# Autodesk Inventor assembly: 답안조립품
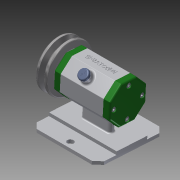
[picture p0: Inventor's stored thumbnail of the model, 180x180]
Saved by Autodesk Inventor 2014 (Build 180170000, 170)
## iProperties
Created: 2018-06
Part Number: 답안조립품
Document SubType Name: Assembly
Designer: geosung1
Author: geosung1
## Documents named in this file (16)
- C:\Users\geosung1\Desktop\480608V1005\답안조립품.iam
- C:\Users\geosung1\Desktop\480608V1005\본체.ipt
- C:\Users\geosung1\Desktop\480608V1005\베어링 15x32x9.ipt
- C:\Users\geosung1\Desktop\480608V1005\축.ipt
- C:\Users\geosung1\Desktop\480608V1005\뒤커버.ipt
- C:\Users\geosung1\Desktop\480608V1005\앞커버.ipt
- C:\Users\geosung1\Desktop\480608V1005\볼트 M4x12.ipt
- C:\Users\geosung1\Desktop\480608V1005\오일 실 15 25 7.ipt
- C:\Users\geosung1\Desktop\480608V1005\V벨트풀리.ipt
- C:\Users\geosung1\Desktop\480608V1005\키 3x3x12.ipt
- 키 3x3x12.ipt
- C:\Users\geosung1\Desktop\480608V1005\너트 M8.ipt
- 너트 M8.ipt
- C:\Users\geosung1\Desktop\480608V1005\스프링와셔 8.ipt
- C:\Users\geosung1\Desktop\480608V1005\와셔 8x17.ipt
- C:\Users\geosung1\Desktop\480608V1005\고무캡.ipt
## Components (2 placed, 2 different names)
1. V벨트풀리:1
2. 고무캡:1
